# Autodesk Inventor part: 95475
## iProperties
Author: Administrator
Shininess: 64.0
Angle Display Precision: 2
Document Length Units: 11272
Document Angle Units: 11286
Document Time Units: 11279
Document Mass Units: 11290
Document Length Units Precision: 3
Document Angle Units Precision: 2
Compacted: True
PropertySet Name: _Private Model Information
Created: 2002-04
Part Number: 95475
Material: Stainless Steel, 440C
Document SubType Name: Modeling
Designer: Administrator
Control State: 0
Master: False
Checked Out: False
PropertySet Name: Design Tracking Control
Density: 0.0
Volumn: 0.0
Area: 0.0
PropertySet Name: Model Information
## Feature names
1. Revolution1
